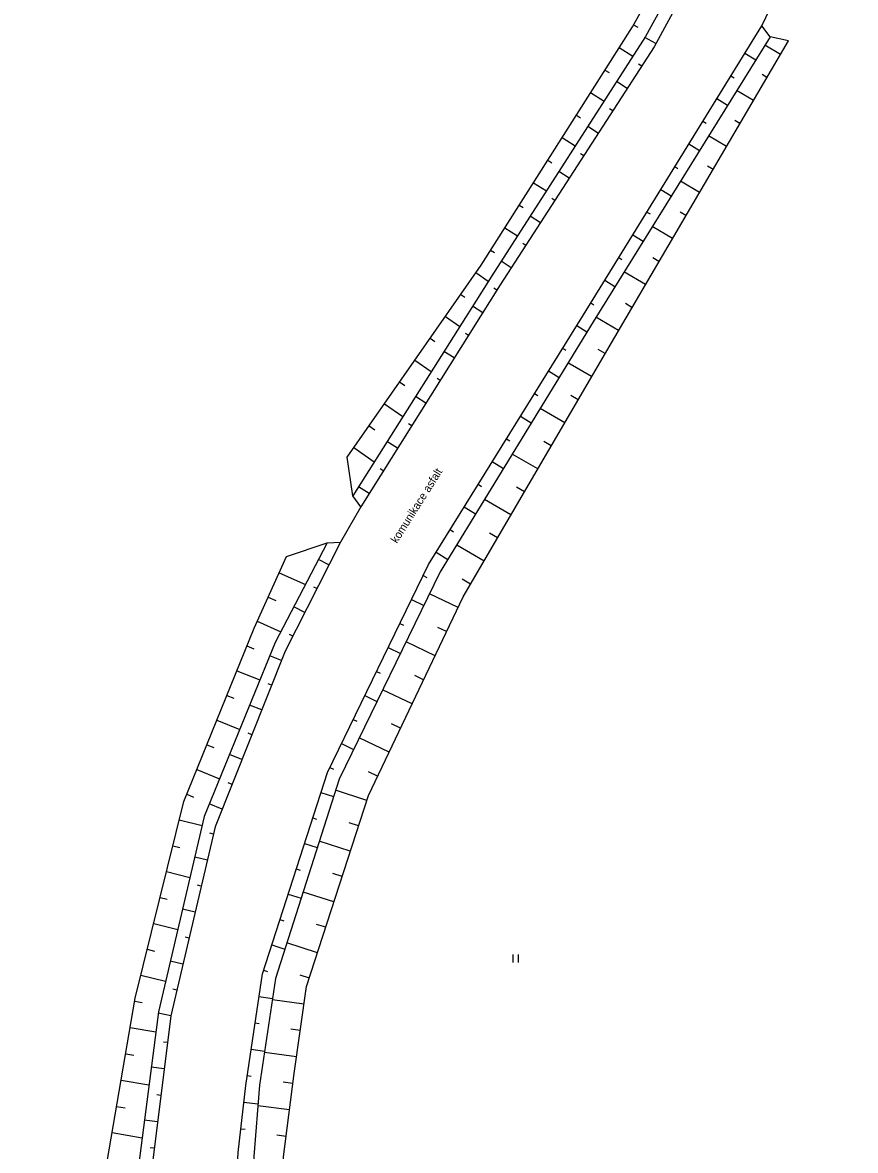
# Model space of a CAD drawing. Extents: x -736968 to -735769, y -1144202 to -1143352.
# Drawn here: x -736622.7 to -736544.7, y -1143956.7 to -1143851 of the extents above; entities that cross this region are included whole.
import ezdxf

# ---------------------------------------------------------------- set-up
doc = ezdxf.new("R2010")
doc.units = 0
for name, color, linetype in [('Vrstva 1', 7, 'Continuous'), ('Vrstva 10', 7, 'Continuous'), ('Vrstva 12', 7, 'Continuous'), ('Vrstva 14', 7, 'Continuous'), ('Vrstva 3', 7, 'Continuous'), ('Vrstva 9', 7, 'Continuous')]:
    doc.layers.add(name, color=color, linetype=linetype)

# ---------------------------------------------------------------- blocks, each defined once
blk = doc.blocks.new('3.060')
at = {"layer": 'Vrstva 1'}
for p, q in [((-0.5, -0.75), (-0.5, 0.75)), ((0.5, -0.75), (0.5, 0.75))]:
    blk.add_line(p, q, dxfattribs=at)

msp = doc.modelspace()

# ---------------------------------------------------------------- linework, layer by layer
at = {"layer": 'Vrstva 10'}
for points in [[(-736551.47, -1143829.95), (-736555.7, -1143838.78), (-736563.57, -1143853.28), (-736578, -1143875.6), (-736591.07, -1143896.38), (-736592.95, -1143899.7), (-736598.15, -1143909.91), (-736604.69, -1143926.37), (-736608.86, -1143944.11), (-736610.96, -1143960.86), (-736610.89, -1143965.89), (-736610.73, -1143973.33), (-736610.14, -1143991.2), (-736610.37, -1143991.77)], [(-736603.22, -1143984.48), (-736603.44, -1143984.1), (-736603.34, -1143971.82), (-736602.56, -1143956.91), (-736601.84, -1143950.63), (-736600.28, -1143940.16), (-736594.19, -1143921.3), (-736584.72, -1143901.79), (-736570.2, -1143878.39), (-736553.51, -1143851.32), (-736544.73, -1143833.02)]]:
    msp.add_lwpolyline(points, dxfattribs=at)
at = {"layer": 'Vrstva 12'}
for points in [[(-736565.52, -1143851.23), (-736565.12, -1143851.45)], [(-736563.41, -1143852.98), (-736564.45, -1143852.41)], [(-736566.85, -1143853.35), (-736565.57, -1143854.16)], [(-736555.08, -1143853.87), (-736554.06, -1143854.5)], [(-736551.75, -1143853.99), (-736553.22, -1143853.13)], [(-736564.74, -1143855.09), (-736565.04, -1143854.89)], [(-736568.19, -1143855.46), (-736567.81, -1143855.7)], [(-736556.39, -1143856), (-736556.09, -1143856.18)], [(-736553.02, -1143856.15), (-736553.47, -1143855.88)], [(-736566.1, -1143857.19), (-736567.1, -1143856.54)], [(-736569.53, -1143857.57), (-736568.28, -1143858.36)], [(-736554.28, -1143858.3), (-736555.86, -1143857.38)], [(-736567.46, -1143859.29), (-736567.76, -1143859.1)], [(-736557.71, -1143858.12), (-736556.7, -1143858.74)], [(-736570.86, -1143859.68), (-736570.49, -1143859.92)], [(-736555.55, -1143860.46), (-736556.03, -1143860.18)], [(-736568.81, -1143861.39), (-736569.81, -1143860.75)], [(-736559.02, -1143860.25), (-736558.72, -1143860.44)], [(-736572.2, -1143861.79), (-736570.98, -1143862.57)], [(-736556.81, -1143862.62), (-736558.49, -1143861.63)], [(-736570.17, -1143863.49), (-736570.47, -1143863.3)], [(-736560.33, -1143862.38), (-736559.34, -1143862.99)], [(-736573.54, -1143863.91), (-736573.18, -1143864.14)], [(-736571.53, -1143865.59), (-736572.51, -1143864.95)], [(-736561.64, -1143864.51), (-736561.35, -1143864.69)], [(-736558.07, -1143864.78), (-736558.6, -1143864.47)], [(-736574.88, -1143866.02), (-736573.68, -1143866.78)], [(-736559.34, -1143866.93), (-736561.13, -1143865.88)], [(-736572.88, -1143867.69), (-736573.18, -1143867.5)], [(-736562.95, -1143866.64), (-736561.98, -1143867.24)], [(-736576.22, -1143868.13), (-736575.86, -1143868.35)], [(-736574.24, -1143869.79), (-736575.21, -1143869.16)], [(-736564.27, -1143868.77), (-736563.97, -1143868.94)], [(-736560.6, -1143869.09), (-736561.16, -1143868.76)], [(-736577.56, -1143870.24), (-736576.39, -1143870.98)], [(-736561.86, -1143871.25), (-736563.77, -1143870.13)], [(-736575.6, -1143871.89), (-736575.89, -1143871.7)], [(-736565.58, -1143870.89), (-736564.61, -1143871.49)], [(-736578.9, -1143872.35), (-736578.55, -1143872.57)], [(-736576.96, -1143873.99), (-736577.92, -1143873.37)], [(-736566.89, -1143873.02), (-736566.6, -1143873.2)], [(-736563.13, -1143873.4), (-736563.72, -1143873.06)], [(-736580.27, -1143874.44), (-736579.12, -1143875.24)], [(-736564.39, -1143875.56), (-736566.41, -1143874.38)], [(-736578.31, -1143876.09), (-736578.6, -1143875.91)], [(-736568.2, -1143875.15), (-736567.25, -1143875.74)], [(-736581.7, -1143876.49), (-736581.32, -1143876.75)], [(-736579.64, -1143878.21), (-736580.6, -1143877.6)], [(-736569.51, -1143877.28), (-736569.23, -1143877.45)], [(-736565.66, -1143877.72), (-736566.28, -1143877.35)], [(-736583.13, -1143878.54), (-736581.79, -1143879.48)], [(-736566.92, -1143879.87), (-736569.05, -1143878.63)], [(-736580.97, -1143880.32), (-736581.26, -1143880.14)], [(-736570.83, -1143879.4), (-736569.88, -1143879.99)], [(-736584.56, -1143880.59), (-736584.13, -1143880.89)], [(-736582.3, -1143882.44), (-736583.27, -1143881.83)], [(-736572.15, -1143881.53), (-736571.86, -1143881.71)], [(-736568.18, -1143882.03), (-736568.83, -1143881.65)], [(-736585.99, -1143882.64), (-736584.46, -1143883.71)], [(-736569.44, -1143884.19), (-736571.66, -1143882.9)], [(-736583.63, -1143884.55), (-736583.92, -1143884.37)], [(-736573.47, -1143883.65), (-736572.49, -1143884.26)], [(-736587.42, -1143884.69), (-736586.93, -1143885.03)], [(-736584.96, -1143886.67), (-736585.94, -1143886.06)], [(-736574.78, -1143885.78), (-736574.49, -1143885.96)], [(-736570.7, -1143886.35), (-736571.38, -1143885.96)], [(-736588.85, -1143886.74), (-736587.13, -1143887.94)], [(-736571.96, -1143888.51), (-736574.27, -1143887.17)], [(-736586.29, -1143888.79), (-736586.59, -1143888.6)], [(-736576.1, -1143887.9), (-736575.09, -1143888.53)], [(-736590.28, -1143888.79), (-736589.74, -1143889.17)], [(-736591.72, -1143890.84), (-736589.8, -1143892.18)], [(-736587.63, -1143890.9), (-736588.61, -1143890.28)], [(-736577.42, -1143890.02), (-736577.11, -1143890.22)], [(-736573.22, -1143890.67), (-736573.92, -1143890.26)], [(-736574.48, -1143892.83), (-736576.87, -1143891.44)], [(-736588.96, -1143893.02), (-736589.25, -1143892.83)], [(-736578.74, -1143892.15), (-736577.7, -1143892.79)], [(-736590.29, -1143895.14), (-736591.28, -1143894.51)], [(-736580.06, -1143894.27), (-736579.74, -1143894.47)], [(-736575.74, -1143894.99), (-736576.47, -1143894.56)], [(-736577, -1143897.15), (-736579.48, -1143895.7)], [(-736581.37, -1143896.4), (-736580.31, -1143897.06)], [(-736582.69, -1143898.52), (-736582.37, -1143898.72)], [(-736578.26, -1143899.31), (-736579.01, -1143898.87)], [(-736579.52, -1143901.47), (-736582.08, -1143899.97)], [(-736594.04, -1143901.83), (-736595.03, -1143901.33)], [(-736584.01, -1143900.65), (-736582.91, -1143901.33)], [(-736598.7, -1143902.57), (-736596.25, -1143903.68)], [(-736585.22, -1143902.83), (-736584.88, -1143903)], [(-736580.77, -1143903.63), (-736581.56, -1143903.17)], [(-736595.17, -1143904.06), (-736595.47, -1143903.91)], [(-736581.95, -1143905.83), (-736584.63, -1143904.56)], [(-736599.73, -1143904.85), (-736599.03, -1143905.16)], [(-736586.32, -1143905.08), (-736585.16, -1143905.64)], [(-736596.31, -1143906.29), (-736597.34, -1143905.76)], [(-736600.77, -1143907.12), (-736598.56, -1143908.12)], [(-736587.41, -1143907.33), (-736587.06, -1143907.49)], [(-736583.03, -1143908.09), (-736583.84, -1143907.7)], [(-736597.44, -1143908.52), (-736597.75, -1143908.36)], [(-736601.73, -1143909.43), (-736601.08, -1143909.69)], [(-736588.5, -1143909.58), (-736587.35, -1143910.13)], [(-736584.1, -1143910.35), (-736586.82, -1143909.05)], [(-736598.5, -1143910.78), (-736599.58, -1143910.35)], [(-736602.67, -1143911.75), (-736600.51, -1143912.62)], [(-736589.59, -1143911.82), (-736589.25, -1143911.99)], [(-736599.42, -1143913.1), (-736599.75, -1143912.97)], [(-736585.18, -1143912.6), (-736586, -1143912.21)], [(-736603.61, -1143914.06), (-736602.96, -1143914.32)], [(-736590.68, -1143914.07), (-736589.55, -1143914.62)], [(-736586.26, -1143914.86), (-736589.02, -1143913.54)], [(-736600.34, -1143915.43), (-736601.47, -1143914.98)], [(-736604.55, -1143916.38), (-736602.4, -1143917.25)], [(-736591.77, -1143916.32), (-736591.44, -1143916.49)], [(-736587.33, -1143917.12), (-736588.17, -1143916.72)], [(-736601.27, -1143917.75), (-736601.61, -1143917.61)], [(-736588.41, -1143919.37), (-736591.21, -1143918.04)], [(-736605.48, -1143918.7), (-736604.84, -1143918.96)], [(-736592.87, -1143918.57), (-736591.74, -1143919.12)], [(-736602.19, -1143920.07), (-736603.36, -1143919.61)], [(-736606.42, -1143921.01), (-736604.28, -1143921.88)], [(-736593.96, -1143920.82), (-736593.62, -1143920.98)], [(-736589.48, -1143921.63), (-736590.33, -1143921.23)], [(-736603.11, -1143922.4), (-736603.47, -1143922.25)], [(-736607.36, -1143923.33), (-736606.72, -1143923.59)], [(-736594.79, -1143923.17), (-736593.62, -1143923.55)], [(-736590.5, -1143923.91), (-736593.44, -1143922.96)], [(-736604.03, -1143924.72), (-736605.25, -1143924.24)], [(-736608.06, -1143925.73), (-736605.92, -1143926.26)], [(-736595.56, -1143925.55), (-736595.21, -1143925.67)], [(-736591.27, -1143926.29), (-736592.15, -1143926)], [(-736604.86, -1143927.07), (-736605.21, -1143926.99)], [(-736592.04, -1143928.67), (-736594.95, -1143927.72)], [(-736608.66, -1143928.15), (-736608.01, -1143928.31)], [(-736596.33, -1143927.93), (-736595.14, -1143928.31)], [(-736605.43, -1143929.51), (-736606.62, -1143929.23)], [(-736609.26, -1143930.58), (-736607.06, -1143931.12)], [(-736597.1, -1143930.31), (-736596.74, -1143930.43)], [(-736592.81, -1143931.05), (-736593.68, -1143930.76)], [(-736606, -1143931.94), (-736606.36, -1143931.86)], [(-736609.86, -1143933.01), (-736609.19, -1143933.17)], [(-736597.87, -1143932.69), (-736596.66, -1143933.08)], [(-736593.58, -1143933.42), (-736596.47, -1143932.49)], [(-736606.57, -1143934.38), (-736607.76, -1143934.1)], [(-736598.64, -1143935.07), (-736598.27, -1143935.19)], [(-736610.46, -1143935.44), (-736608.21, -1143935.99)], [(-736594.35, -1143935.8), (-736595.21, -1143935.52)], [(-736607.14, -1143936.81), (-736607.5, -1143936.73)], [(-736595.12, -1143938.18), (-736597.98, -1143937.25)], [(-736611.06, -1143937.86), (-736610.37, -1143938.03)], [(-736599.4, -1143937.45), (-736598.17, -1143937.84)], [(-736607.72, -1143939.24), (-736608.91, -1143938.96)], [(-736611.66, -1143940.29), (-736609.35, -1143940.86)], [(-736600.17, -1143939.83), (-736599.8, -1143939.95)], [(-736595.88, -1143940.56), (-736596.74, -1143940.28)], [(-736608.29, -1143941.68), (-736608.65, -1143941.59)], [(-736600.6, -1143942.28), (-736599.33, -1143942.47)], [(-736596.38, -1143943), (-736599.34, -1143942.58)], [(-736612.24, -1143942.72), (-736611.53, -1143942.84)], [(-736608.86, -1143944.11), (-736610.04, -1143943.83)], [(-736600.97, -1143944.76), (-736600.59, -1143944.81)], [(-736612.66, -1143945.18), (-736610.26, -1143945.6)], [(-736596.73, -1143945.48), (-736597.62, -1143945.35)], [(-736609.17, -1143946.59), (-736609.53, -1143946.55)], [(-736613.08, -1143947.65), (-736612.33, -1143947.78)], [(-736601.33, -1143947.23), (-736600.07, -1143947.42)], [(-736597.08, -1143947.95), (-736600.09, -1143947.52)], [(-736609.48, -1143949.07), (-736610.7, -1143948.92)], [(-736601.7, -1143949.7), (-736601.33, -1143949.76)], [(-736613.51, -1143950.11), (-736610.91, -1143950.56)], [(-736597.42, -1143950.43), (-736598.34, -1143950.31)], [(-736609.79, -1143951.55), (-736610.16, -1143951.51)], [(-736602.02, -1143952.18), (-736600.69, -1143952.33)], [(-736613.93, -1143952.58), (-736613.12, -1143952.71)], [(-736597.74, -1143952.91), (-736600.71, -1143952.53)], [(-736610.1, -1143954.03), (-736611.34, -1143953.88)], [(-736614.35, -1143955.04), (-736611.55, -1143955.52)], [(-736602.3, -1143954.67), (-736601.88, -1143954.71)], [(-736598.06, -1143955.39), (-736598.92, -1143955.28)], [(-736610.42, -1143956.51), (-736610.79, -1143956.47)]]:
    msp.add_lwpolyline(points, dxfattribs=at)
at = {"layer": 'Vrstva 9'}
for points in [[(-736591.07, -1143896.38), (-736591.82, -1143895.37), (-736592.35, -1143891.75), (-736579.77, -1143873.73), (-736565.62, -1143851.41), (-736557.95, -1143837.69), (-736553.84, -1143829.15)], [(-736552.6, -1143829.77), (-736556.66, -1143838.22), (-736564.38, -1143852.3), (-736578.8, -1143874.74), (-736591.82, -1143895.37)], [(-736551.01, -1143852.72), (-736552.73, -1143852.35), (-736553.51, -1143851.32)], [(-736552.73, -1143852.35), (-736569.31, -1143879.05), (-736583.62, -1143902.49), (-736593.1, -1143921.9), (-736599.04, -1143940.58), (-736600.55, -1143950.58), (-736601.09, -1143957.27), (-736600.37, -1143986.17)], [(-736598.04, -1143984.56), (-736598.31, -1143957.31), (-736597.3, -1143949.49), (-736596.14, -1143941.35), (-736590.35, -1143923.45), (-736581.48, -1143904.84), (-736567.28, -1143880.49), (-736551.01, -1143852.72)], [(-736594.22, -1143899.77), (-736599.08, -1143909.12), (-736605.72, -1143925.4), (-736610.02, -1143943.71), (-736612.3, -1143961.3), (-736612.48, -1143965.92), (-736611.24, -1143991.89)], [(-736598.01, -1143901.06), (-736594.22, -1143899.77), (-736592.95, -1143899.7)], [(-736622.74, -1144000), (-736621.33, -1143998.01), (-736613.57, -1143991.64), (-736614.4, -1143966.27), (-736615.57, -1143962.11), (-736612.19, -1143942.45), (-736607.63, -1143924), (-736601.06, -1143907.77), (-736598.01, -1143901.06)]]:
    msp.add_lwpolyline(points, dxfattribs=at)

# ---------------------------------------------------------------- block references
at = {"layer": 'Vrstva 3', "xscale": 0.5, "yscale": 0.5}
msp.add_blockref('3.060', (-736576.54, -1143938.73), dxfattribs=at)

# ---------------------------------------------------------------- texts
at = {"layer": 'Vrstva 14'}
msp.add_text('komunikace asfalt', height=0.75, rotation=57.759, dxfattribs=at).set_placement((-736587.67, -1143899.87))

doc.saveas('drawing.dxf')
